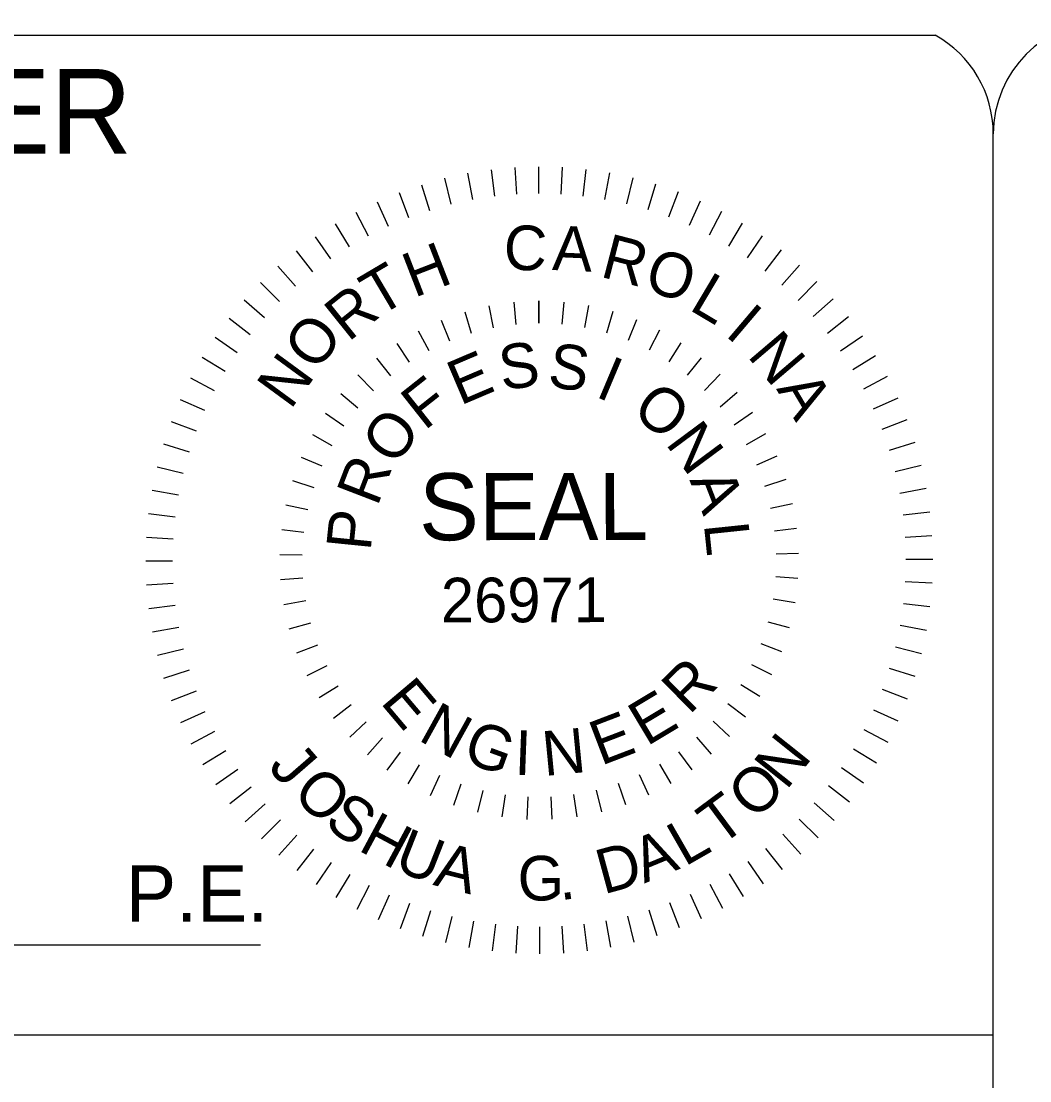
# Model space of a CAD drawing. Extents: x 2110629 to 2114002, y 669321 to 671542.
# Drawn here: x 2113039.5 to 2113193.7, y 669847.8 to 670009.7 of the extents above; entities that cross this region are included whole.
import ezdxf

# ---------------------------------------------------------------- set-up
doc = ezdxf.new("R2010")
doc.units = 0
doc.layers.add('Default', color=7, linetype='Continuous')
doc.layers.add('Exist Structure Minor Catch Basin', color=7, linetype='Continuous')

msp = doc.modelspace()

# ---------------------------------------------------------------- linework, layer by layer
at = {"layer": 'Default'}
for p, q in [((2113111.35, 669987.02), (2113111.85, 669982.96)), ((2113114.96, 669987.36), (2113115.22, 669983.27)), ((2113118.59, 669987.48), (2113118.6, 669983.38)), ((2113122.23, 669987.38), (2113121.99, 669983.29)), ((2113125.84, 669987.05), (2113125.36, 669982.99)), ((2113129.43, 669986.52), (2113128.7, 669982.49)), ((2113104.21, 669985.71), (2113105.19, 669981.73)), ((2113107.76, 669986.48), (2113108.5, 669982.45)), ((2113132.98, 669985.76), (2113132.02, 669981.78)), ((2113097.28, 669983.54), (2113098.75, 669979.7)), ((2113100.71, 669984.73), (2113101.94, 669980.81)), ((2113136.49, 669984.79), (2113135.28, 669980.87)), ((2113139.92, 669983.62), (2113138.47, 669979.78)), ((2113093.93, 669982.13), (2113095.62, 669978.4)), ((2113143.28, 669982.22), (2113141.61, 669978.49)), ((2113090.67, 669980.54), (2113092.58, 669976.91)), ((2113146.55, 669980.65), (2113144.65, 669977.01)), ((2113087.51, 669978.75), (2113089.64, 669975.25)), ((2113149.72, 669978.87), (2113147.6, 669975.36)), ((2113152.77, 669976.9), (2113150.45, 669973.53)), ((2113084.46, 669976.77), (2113086.8, 669973.41)), ((2113081.54, 669974.62), (2113084.07, 669971.39)), ((2113155.69, 669974.76), (2113153.18, 669971.52)), ((2113078.75, 669972.28), (2113081.48, 669969.22)), ((2113158.49, 669972.43), (2113155.78, 669969.36)), ((2113076.12, 669969.79), (2113079.02, 669966.9)), ((2113161.14, 669969.95), (2113158.25, 669967.05)), ((2113073.63, 669967.14), (2113076.7, 669964.43)), ((2113163.63, 669967.31), (2113160.57, 669964.59)), ((2113111.02, 669966.23), (2113111.68, 669962.88)), ((2113114.81, 669966.79), (2113115.14, 669963.39)), ((2113118.63, 669966.98), (2113118.64, 669963.57)), ((2113118.64, 669963.57), (2113118.63, 669966.98)), ((2113122.46, 669966.8), (2113122.14, 669963.41)), ((2113126.25, 669966.26), (2113125.6, 669962.9)), ((2113071.31, 669964.34), (2113074.54, 669961.83)), ((2113103.7, 669964.03), (2113104.99, 669960.87)), ((2113107.31, 669965.31), (2113108.29, 669962.03)), ((2113129.96, 669965.35), (2113129, 669962.07)), ((2113133.58, 669964.09), (2113132.3, 669960.92)), ((2113165.97, 669964.52), (2113162.74, 669961.99)), ((2113100.23, 669962.41), (2113101.82, 669959.39)), ((2113137.06, 669962.48), (2113135.48, 669959.45)), ((2113069.17, 669961.42), (2113072.54, 669959.1)), ((2113168.12, 669961.61), (2113164.76, 669959.27)), ((2113096.93, 669960.46), (2113098.81, 669957.6)), ((2113140.36, 669960.55), (2113138.5, 669957.68)), ((2113067.2, 669958.37), (2113070.71, 669956.25)), ((2113093.83, 669958.2), (2113095.98, 669955.54)), ((2113143.46, 669958.3), (2113141.33, 669955.63)), ((2113170.1, 669958.56), (2113166.6, 669956.43)), ((2113146.33, 669955.76), (2113143.95, 669953.31)), ((2113065.42, 669955.2), (2113069.05, 669953.3)), ((2113090.98, 669955.66), (2113093.37, 669953.22)), ((2113171.89, 669955.4), (2113168.26, 669953.49)), ((2113088.38, 669952.85), (2113090.99, 669950.66)), ((2113148.94, 669952.97), (2113146.34, 669950.76)), ((2113063.84, 669951.93), (2113067.58, 669950.26)), ((2113173.48, 669952.13), (2113169.75, 669950.45)), ((2113086.05, 669949.81), (2113088.87, 669947.87)), ((2113151.28, 669949.93), (2113148.47, 669947.98)), ((2113062.45, 669948.57), (2113066.29, 669947.12)), ((2113174.89, 669948.78), (2113171.05, 669947.32)), ((2113084.04, 669946.55), (2113087.03, 669944.89)), ((2113153.3, 669946.68), (2113150.32, 669945.01)), ((2113061.27, 669945.14), (2113065.19, 669943.93)), ((2113176.08, 669945.36), (2113172.16, 669944.13)), ((2113082.35, 669943.11), (2113085.48, 669941.76)), ((2113155.01, 669943.25), (2113151.88, 669941.88)), ((2113060.3, 669941.63), (2113064.29, 669940.67)), ((2113177.06, 669941.85), (2113173.08, 669940.87)), ((2113156.37, 669939.67), (2113153.12, 669938.62)), ((2113059.55, 669938.08), (2113063.58, 669937.35)), ((2113081, 669939.53), (2113084.25, 669938.49)), ((2113177.83, 669938.31), (2113173.8, 669937.56)), ((2113080, 669935.84), (2113083.34, 669935.11)), ((2113157.38, 669935.98), (2113154.05, 669935.24)), ((2113178.37, 669934.72), (2113174.31, 669934.22)), ((2113059.01, 669934.49), (2113063.08, 669934.01)), ((2113079.36, 669932.06), (2113082.75, 669931.66)), ((2113158.03, 669932.21), (2113154.65, 669931.79)), ((2113058.69, 669930.88), (2113062.78, 669930.64)), ((2113178.71, 669931.1), (2113174.62, 669930.85)), ((2113079.09, 669928.24), (2113082.5, 669928.16)), ((2113158.32, 669928.39), (2113154.91, 669928.3)), ((2113058.59, 669927.24), (2113062.69, 669927.25)), ((2113178.83, 669927.47), (2113174.73, 669927.46)), ((2113058.7, 669923.61), (2113062.79, 669923.87)), ((2113079.19, 669924.41), (2113082.6, 669924.67)), ((2113158.23, 669924.56), (2113154.83, 669924.8)), ((2113178.73, 669923.84), (2113174.64, 669924.08)), ((2113059.04, 669920), (2113063.1, 669920.5)), ((2113079.67, 669920.61), (2113083.03, 669921.19)), ((2113154.43, 669921.45), (2113157.8, 669920.89)), ((2113178.4, 669920.22), (2113174.34, 669920.71)), ((2113059.59, 669916.41), (2113063.62, 669917.15)), ((2113080.49, 669916.87), (2113083.78, 669917.78)), ((2113156.96, 669917.02), (2113153.67, 669917.91)), ((2113177.87, 669916.63), (2113173.84, 669917.36)), ((2113060.36, 669912.86), (2113064.34, 669913.84)), ((2113081.69, 669913.23), (2113084.88, 669914.45)), ((2113155.78, 669913.37), (2113152.59, 669914.58)), ((2113177.11, 669913.08), (2113173.13, 669914.05)), ((2113061.34, 669909.36), (2113065.26, 669910.59)), ((2113083.22, 669909.73), (2113086.28, 669911.25)), ((2113154.26, 669909.87), (2113151.2, 669911.38)), ((2113176.14, 669909.58), (2113172.22, 669910.79)), ((2113062.53, 669905.93), (2113066.36, 669907.4)), ((2113085.09, 669906.39), (2113087.99, 669908.19)), ((2113152.41, 669906.52), (2113149.5, 669908.31)), ((2113174.97, 669906.15), (2113171.13, 669907.59)), ((2113063.93, 669902.58), (2113067.66, 669904.27)), ((2113087.27, 669903.24), (2113089.98, 669905.32)), ((2113150.24, 669903.36), (2113147.52, 669905.42)), ((2113173.57, 669902.79), (2113169.84, 669904.46)), ((2113089.74, 669900.32), (2113092.24, 669902.65)), ((2113147.77, 669900.43), (2113145.27, 669902.75)), ((2113065.52, 669899.32), (2113069.15, 669901.23)), ((2113172, 669899.52), (2113168.36, 669901.42)), ((2113092.48, 669897.65), (2113094.75, 669900.21)), ((2113145.04, 669897.75), (2113142.77, 669900.3)), ((2113067.32, 669896.16), (2113070.82, 669898.29)), ((2113095.48, 669895.26), (2113097.48, 669898.02)), ((2113142.06, 669895.35), (2113140.05, 669898.1)), ((2113170.22, 669896.35), (2113166.71, 669898.47)), ((2113098.68, 669893.17), (2113100.41, 669896.12)), ((2113138.86, 669893.24), (2113137.12, 669896.18)), ((2113069.29, 669893.11), (2113072.66, 669895.44)), ((2113102.08, 669891.39), (2113103.51, 669894.5)), ((2113135.47, 669891.46), (2113134.03, 669894.55)), ((2113168.25, 669893.3), (2113164.88, 669895.62)), ((2113071.45, 669890.19), (2113074.67, 669892.72)), ((2113105.63, 669889.95), (2113106.76, 669893.18)), ((2113131.93, 669890), (2113130.79, 669893.23)), ((2113166.11, 669890.37), (2113162.88, 669892.89)), ((2113110.09, 669892.19), (2113109.27, 669888.87)), ((2113113.06, 669888.14), (2113113.54, 669891.52)), ((2113116.87, 669887.77), (2113117.02, 669891.19)), ((2113120.7, 669887.78), (2113120.53, 669891.19)), ((2113124.51, 669888.16), (2113124.01, 669891.54)), ((2113128.26, 669888.9), (2113127.44, 669892.22)), ((2113073.78, 669887.4), (2113076.84, 669890.13)), ((2113163.78, 669887.57), (2113160.71, 669890.29)), ((2113161.3, 669884.93), (2113158.4, 669887.82)), ((2113076.28, 669884.77), (2113079.17, 669887.67)), ((2113078.92, 669882.28), (2113081.64, 669885.35)), ((2113158.66, 669882.43), (2113155.94, 669885.49)), ((2113081.72, 669879.96), (2113084.24, 669883.19)), ((2113155.87, 669880.1), (2113153.34, 669883.32)), ((2113152.95, 669877.94), (2113150.62, 669881.31)), ((2113084.65, 669877.82), (2113086.97, 669881.19)), ((2113087.7, 669875.85), (2113089.82, 669879.36)), ((2113149.91, 669875.97), (2113147.78, 669879.47)), ((2113090.87, 669874.07), (2113092.77, 669877.7)), ((2113146.75, 669874.17), (2113144.84, 669877.8)), ((2113094.14, 669872.49), (2113095.81, 669876.23)), ((2113097.5, 669871.1), (2113098.94, 669874.94)), ((2113140.13, 669871.18), (2113138.67, 669875.01)), ((2113143.48, 669872.58), (2113141.8, 669876.31)), ((2113100.93, 669869.92), (2113102.14, 669873.84)), ((2113136.71, 669869.99), (2113135.48, 669873.91)), ((2113104.43, 669868.95), (2113105.4, 669872.94)), ((2113107.98, 669868.2), (2113108.71, 669872.23)), ((2113111.57, 669867.66), (2113112.06, 669871.73)), ((2113126.07, 669867.69), (2113125.57, 669871.75)), ((2113129.66, 669868.24), (2113128.91, 669872.27)), ((2113133.2, 669869.01), (2113132.22, 669872.99)), ((2113115.19, 669867.34), (2113115.43, 669871.43)), ((2113118.82, 669867.24), (2113118.81, 669871.34)), ((2113122.45, 669867.35), (2113122.2, 669871.44))]:
    msp.add_line(p, q, dxfattribs=at)
at = {"layer": 'Exist Structure Minor Catch Basin'}
for p, q in [((2112826.8, 670007.62), (2113179.19, 670007.56)), ((2113188.03, 669717.1), (2113188.08, 669992.5)), ((2112827.84, 669868.64), (2113076.13, 669868.6)), ((2112816.51, 669854.9), (2113188.06, 669854.84))]:
    msp.add_line(p, q, dxfattribs=at)
for centre, start, end in [((2113205.29, 669992.49), 89.9903, 179.9903), ((2113170.87, 669992.5), 359.9903, 61.0741)]:
    msp.add_arc(centre, 17.21, start, end, dxfattribs=at)

# ---------------------------------------------------------------- texts
at = {"layer": 'Default'}
for s, height, rotation, p in [('C', 6.82, 357.4652, (2113113.16, 669971.82)), ('A', 6.82, 357.4652, (2113120.62, 669971.7)), ('R', 6.82, 345.4559, (2113127.85, 669970.71)), ('H', 6.82, 21.1759, (2113099.59, 669967.41)), ('O', 6.82, 342.3991, (2113134.47, 669968.75)), ('T', 6.82, 30.6078, (2113094.1, 669964.43)), ('L', 6.82, 329.2628, (2113141.42, 669965.73)), ('R', 6.82, 38.7688, (2113089.52, 669960.6)), ('I', 6.82, 319.6873, (2113146.93, 669961.78)), ('O', 6.82, 51.8255, (2113084.58, 669955.99)), ('N', 6.82, 310.3929, (2113150.36, 669958.57)), ('S', 6.82, 7.7563, (2113113.03, 669953.3)), ('E', 6.82, 23.0526, (2113106.62, 669950.94)), ('S', 6.82, 352.4601, (2113119.84, 669953.88)), ('N', 6.82, 53.785, (2113080.68, 669950.22)), ('I', 6.82, 337.1639, (2113127.1, 669952.42)), ('F', 6.82, 38.3488, (2113101.17, 669947.07)), ('A', 6.82, 300.6253, (2113154.87, 669953.54)), ('O', 6.82, 321.8676, (2113132.61, 669949.77)), ('O', 6.82, 53.6451, (2113096.64, 669941.56)), ('N', 6.82, 306.5714, (2113137.88, 669945.21)), ('R', 6.82, 68.9413, (2113093.95, 669935.42)), ('SEAL', 10.244, 0.1082, (2113100.35, 669930.4)), ('A', 6.82, 291.2751, (2113141.63, 669939.63)), ('P', 6.82, 84.2376, (2113092.93, 669928.66)), ('L', 6.82, 275.9789, (2113143.85, 669932.87)), ('26971', 6.824, 0.1082, (2113103.68, 669917.85)), ('R', 6.82, 44.6731, (2113141.61, 669903.62)), ('E', 6.82, 310.1783, (2113094.29, 669905.64)), ('E', 6.82, 30.902, (2113135.12, 669898.85)), ('N', 6.82, 331.0334, (2113100.03, 669899.96)), ('E', 6.82, 20.9161, (2113128.12, 669895.92)), ('G', 6.82, 339.7996, (2113106.72, 669896.77)), ('I', 6.82, 357.8944, (2113114.85, 669894.6)), ('N', 6.82, 5.5241, (2113119.48, 669894.38)), ('N', 6.82, 51.4058, (2113156.44, 669892.09)), ('J', 6.82, 310.9673, (2113077.11, 669895.7)), ('O', 6.82, 44.0013, (2113151.63, 669887.46)), ('O', 6.82, 317.1776, (2113080.73, 669891.43)), ('S', 6.82, 324.5821, (2113085.61, 669886.88)), ('T', 6.82, 36.5968, (2113146.27, 669883.49)), ('H', 6.82, 331.7477, (2113090.86, 669883.12)), ('U', 6.82, 338.5551, (2113096.25, 669880.18)), ('L', 6.82, 29.7894, (2113140.93, 669880.48)), ('A', 6.82, 22.3849, (2113134.75, 669877.95)), ('A', 6.82, 345.8401, (2113102.35, 669877.77)), ('D', 6.82, 15.2193, (2113128.51, 669876.28)), ('G', 6.82, 0.6492, (2113115.44, 669875.33)), ('.', 6.82, 7.8148, (2113121.9, 669875.38))]:
    msp.add_text(s, height=height, rotation=rotation, dxfattribs=at).set_placement(p)
at = {"layer": 'Exist Structure Minor Catch Basin'}
for s, height, p in [(' HYDRAULICS ENGINEER', 12.9094, (2112845.43, 669989.52)), ('P.E.', 8.605, (2113055.55, 669872.13))]:
    msp.add_text(s, height=height, rotation=359.9903, dxfattribs=at).set_placement(p)

doc.saveas('drawing.dxf')
